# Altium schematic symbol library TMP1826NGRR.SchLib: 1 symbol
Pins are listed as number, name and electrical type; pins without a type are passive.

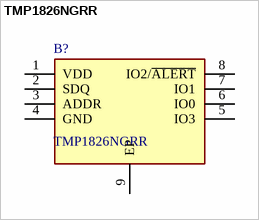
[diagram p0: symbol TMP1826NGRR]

## TMP1826NGRR
designator B?
Board Mount Temperature Sensors 1-Wire +/-0.2C accurate digital temperature sensor with 2-kbit EEPROM; Manufacturer_Name: Texas Instruments; Geometry.Height: 0.8mm
footprint SON50P250X250X80-9N-D
pins: 1 VDD, 2 SDQ, 3 ADDR, 4 GND, 5 IO3, 6 IO0, 7 IO1, 8 IO2/~{ALERT}, 9 EP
